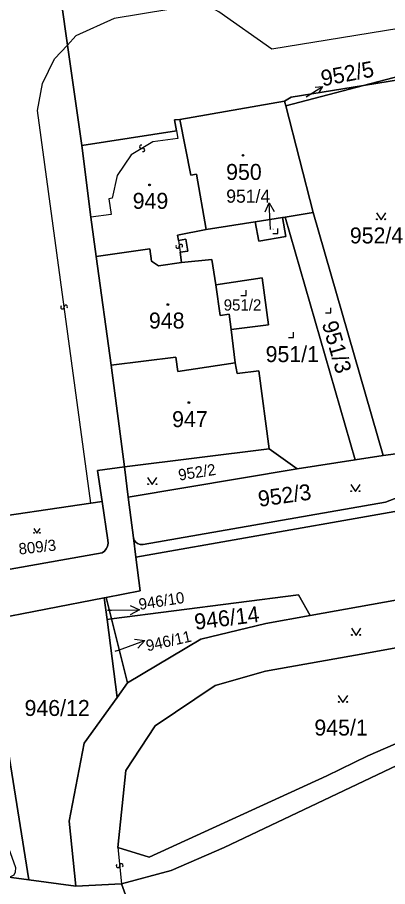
# Model space of a CAD drawing. Extents: x -600309 to -598967, y -1161267 to -1160292.
# Drawn here: x -599244.9 to -599205.5, y -1161220.2 to -1161127.6 of the extents above; entities that cross this region are included whole.
import ezdxf

# ---------------------------------------------------------------- set-up
doc = ezdxf.new("R2010")
doc.units = 0
for name, color, linetype in [('Level 1', 7, 'Continuous'), ('Level 13', 7, 'Continuous'), ('Level 3', 7, 'Continuous'), ('Level 4', 7, 'Continuous'), ('Level 5', 7, 'Continuous'), ('Level 57', 7, 'Continuous'), ('Level 60', 7, 'Continuous'), ('Vrstva 60', 7, 'Continuous')]:
    doc.layers.add(name, color=color, linetype=linetype)

msp = doc.modelspace()

# ---------------------------------------------------------------- linework, layer by layer
at = {"layer": 'Level 1'}
for points in [[(-599240.86, -1161121.69), (-599239.6, -1161130.5)], [(-599166.68, -1161128.1), (-599167.25, -1161124.11), (-599208.04, -1161134.81)], [(-599166.68, -1161128.1), (-599167.3, -1161128.2), (-599208.04, -1161134.81)], [(-599239.6, -1161130.5), (-599238.08, -1161141.2)], [(-599216.47, -1161136.47), (-599215.77, -1161136.06), (-599208.04, -1161134.81)], [(-599216.34, -1161136.99), (-599208.04, -1161134.81)], [(-599227.63, -1161138.44), (-599216.47, -1161136.47)], [(-599216.47, -1161136.47), (-599216.34, -1161136.99)], [(-599213.4, -1161148.37), (-599216.34, -1161136.99)], [(-599227.97, -1161139.66), (-599228.21, -1161138.49), (-599227.63, -1161138.44)], [(-599227.63, -1161138.44), (-599226.44, -1161144.38), (-599225.86, -1161144.27), (-599224.82, -1161150.17)], [(-599238.08, -1161141.2), (-599227.97, -1161139.66)], [(-599238.08, -1161141.2), (-599237.1, -1161148.85)], [(-599213.4, -1161148.37), (-599216.38, -1161148.84)], [(-599213.4, -1161148.37), (-599205.95, -1161174.25)], [(-599237.1, -1161148.85), (-599236.54, -1161153.03)], [(-599219.58, -1161149.34), (-599216.67, -1161148.89)], [(-599216.67, -1161148.89), (-599216.32, -1161150.91), (-599219.22, -1161151.4), (-599219.58, -1161149.34)], [(-599216.67, -1161148.89), (-599216.38, -1161148.84)], [(-599216.38, -1161148.84), (-599208.93, -1161174.71)], [(-599224.82, -1161150.17), (-599227.86, -1161150.77), (-599227.78, -1161151.33)], [(-599224.82, -1161150.17), (-599219.58, -1161149.34)], [(-599227.78, -1161151.33), (-599226.97, -1161151.2), (-599226.79, -1161152.47), (-599227.6, -1161152.59)], [(-599236.54, -1161153.03), (-599230.83, -1161152.22), (-599230.63, -1161153.54), (-599229.9, -1161154.05), (-599227.46, -1161153.69)], [(-599227.6, -1161152.59), (-599227.46, -1161153.69)], [(-599236.54, -1161153.03), (-599234.96, -1161164.64)], [(-599227.46, -1161153.69), (-599224.21, -1161153.36), (-599223.8, -1161156.07)], [(-599223.8, -1161156.07), (-599218.86, -1161155.32), (-599218.19, -1161160.32), (-599222.16, -1161160.82)], [(-599223.8, -1161156.07), (-599223.31, -1161159.32), (-599222.37, -1161159.18), (-599222.16, -1161160.82)], [(-599221.71, -1161164.39), (-599222.16, -1161160.82)], [(-599234.96, -1161164.64), (-599228.06, -1161163.79), (-599227.84, -1161165.3), (-599221.71, -1161164.39)], [(-599234.96, -1161164.64), (-599233.53, -1161175.48)], [(-599221.71, -1161164.39), (-599221.52, -1161165.53), (-599219.21, -1161165.24), (-599218.09, -1161173.54)], [(-599232.57, -1161183.04), (-599232.48, -1161183.29), (-599232.32, -1161183.5), (-599232.14, -1161183.65), (-599231.85, -1161183.75), (-599231.55, -1161183.74), (-599205.71, -1161179.24), (-599203.58, -1161178.41), (-599201.35, -1161176.43), (-599198.94, -1161173.34)], [(-599159.62, -1161172.48), (-599173.52, -1161173.95), (-599178.99, -1161175.18), (-599193.62, -1161178.28), (-599232.3, -1161185.1)], [(-599198.94, -1161173.34), (-599205.95, -1161174.25)], [(-599218.09, -1161173.54), (-599233.53, -1161175.48)], [(-599215.11, -1161175.67), (-599218.09, -1161173.54)], [(-599205.95, -1161174.25), (-599208.93, -1161174.71)], [(-599215.11, -1161175.67), (-599208.93, -1161174.71)], [(-599233.53, -1161175.48), (-599236.4, -1161175.84), (-599235.91, -1161179.17)], [(-599233.53, -1161175.48), (-599233.12, -1161178.7)], [(-599215.11, -1161175.67), (-599233.12, -1161178.7)], [(-599232.57, -1161183.04), (-599233.12, -1161178.7)], [(-599237.12, -1161179.35), (-599249.7, -1161181.2)], [(-599235.91, -1161179.17), (-599235.31, -1161183.28), (-599235.27, -1161183.61), (-599235.33, -1161183.94), (-599235.47, -1161184.22), (-599235.67, -1161184.46), (-599235.92, -1161184.63), (-599248.95, -1161186.94)], [(-599235.91, -1161179.17), (-599237.12, -1161179.35)], [(-599163.1, -1161182.7), (-599163.18, -1161182.24), (-599213.74, -1161191.32)], [(-599232.57, -1161183.04), (-599232.3, -1161185.1)], [(-599235.48, -1161189.38), (-599231.85, -1161188.68), (-599232.3, -1161185.1)], [(-599213.74, -1161191.32), (-599214.99, -1161189.11), (-599234.9, -1161191.67)], [(-599235.69, -1161189.42), (-599248.17, -1161191.83)], [(-599235.48, -1161189.38), (-599235.69, -1161189.42)], [(-599235.69, -1161189.42), (-599235.39, -1161191.73)], [(-599235.48, -1161189.38), (-599234.9, -1161191.67)], [(-599161.82, -1161189.5), (-599186.71, -1161199.25), (-599198.82, -1161204.61), (-599222.89, -1161216.04), (-599228.56, -1161218.5), (-599233.84, -1161219.9)], [(-599234.25, -1161216.06), (-599233.37, -1161207.83), (-599230.27, -1161203.06), (-599223.86, -1161198.78), (-599218.5, -1161197.24), (-599207.91, -1161195.38), (-599204.21, -1161194.67), (-599179.39, -1161190.37), (-599178.01, -1161193.44)], [(-599248.17, -1161191.83), (-599243.72, -1161219.5)], [(-599235.39, -1161191.73), (-599234.9, -1161191.67)], [(-599235.39, -1161191.73), (-599234.32, -1161200.06)], [(-599234.9, -1161191.67), (-599233.19, -1161198.49)], [(-599233.19, -1161198.49), (-599225.39, -1161193.83), (-599218.45, -1161192.16), (-599213.74, -1161191.32)], [(-599178.01, -1161193.44), (-599207.58, -1161206.28), (-599211.95, -1161208.39), (-599230.9, -1161217.06), (-599234.25, -1161216.06)], [(-599233.19, -1161198.49), (-599234.32, -1161200.06)], [(-599238.72, -1161220.17), (-599239.43, -1161213.23), (-599237.82, -1161204.91), (-599234.32, -1161200.06)], [(-599246.09, -1161219.18), (-599243.72, -1161219.5)], [(-599243.72, -1161219.5), (-599238.72, -1161220.17)], [(-599238.72, -1161220.17), (-599233.84, -1161219.9)], [(-599233.84, -1161219.9), (-599223.3, -1161248.82)]]:
    msp.add_lwpolyline(points, dxfattribs=at)
at = {"layer": 'Level 13'}
for centre, start, end in [((-599231.735, -1161141.362), 68.37668, 300.96668), ((-599231.546, -1161141.679), 248.59114, 120.68913), ((-599227.872, -1161151.985), 135.28838, 7.87838), ((-599227.507, -1161151.936), 315.50284, 187.60083), ((-599240.143, -1161158.443), 135.08477, 7.18276), ((-599239.778, -1161158.396), 314.87031, 187.46031), ((-599234.223, -1161217.999), 133.25271, 5.84271), ((-599233.856, -1161217.962), 313.46716, 185.56516)]:
    msp.add_arc(centre, 0.184, start, end, dxfattribs=at)
at = {"layer": 'Level 3'}
for points in [[(-599101.43, -1161117.43), (-599109.99, -1161109.28), (-599114.44, -1161108.57), (-599116.4, -1161108.6), (-599124.79, -1161109.79), (-599126.3, -1161110.5), (-599127.38, -1161111.59), (-599131.31, -1161116.83), (-599217.8, -1161130.93), (-599223.47, -1161126.97), (-599224.65, -1161126.32), (-599225.79, -1161126.22), (-599234.64, -1161127.69), (-599238.7, -1161129.53), (-599239.6, -1161130.5)], [(-599237.12, -1161179.35), (-599242.79, -1161137.48), (-599242.25, -1161134.62), (-599240.97, -1161131.96), (-599239.6, -1161130.5)], [(-599227.97, -1161139.66), (-599227.83, -1161140.47), (-599230.49, -1161140.82), (-599232.8, -1161142.22), (-599234.32, -1161144.41), (-599234.84, -1161146.81), (-599235.2, -1161146.88), (-599234.96, -1161148.55), (-599237.1, -1161148.85)], [(-599227.78, -1161151.33), (-599227.6, -1161152.59)], [(-599234.25, -1161216.06), (-599233.84, -1161219.9)]]:
    msp.add_lwpolyline(points, dxfattribs=at)
at = {"layer": 'Level 5'}
for points in [[(-599206.671, -1161148.38), (-599206.17, -1161149.13), (-599205.67, -1161148.38)], [(-599217.71, -1161150.6), (-599217.16, -1161150.6), (-599217.16, -1161150.05)], [(-599221.11, -1161157.2), (-599220.56, -1161157.2), (-599220.56, -1161156.65)], [(-599212.09, -1161159.05), (-599211.54, -1161159.05), (-599211.54, -1161158.5)], [(-599216.04, -1161161.67), (-599215.49, -1161161.67), (-599215.49, -1161161.12)], [(-599231.061, -1161176.61), (-599230.56, -1161177.36), (-599230.06, -1161176.61)], [(-599209.411, -1161177.36), (-599208.91, -1161178.11), (-599208.41, -1161177.36)], [(-599243.201, -1161182.03), (-599242.86, -1161182.54), (-599242.52, -1161182.03)], [(-599209.341, -1161192.68), (-599208.84, -1161193.43), (-599208.34, -1161192.68)], [(-599210.731, -1161199.83), (-599210.23, -1161200.58), (-599209.73, -1161199.83)]]:
    msp.add_lwpolyline(points, dxfattribs=at)
for centre, radius in [((-599220.89, -1161142.26), 0.09), ((-599220.89, -1161142.26), 0.0521), ((-599230.85, -1161145.41), 0.09), ((-599230.85, -1161145.41), 0.0521), ((-599206.62, -1161149.08), 0.05), ((-599205.721, -1161149.08), 0.05), ((-599228.9, -1161158.17), 0.09), ((-599228.9, -1161158.17), 0.0521), ((-599226.66, -1161168.61), 0.09), ((-599226.66, -1161168.61), 0.0521), ((-599231.01, -1161177.31), 0.05), ((-599230.111, -1161177.31), 0.05), ((-599209.36, -1161178.06), 0.05), ((-599208.461, -1161178.06), 0.05), ((-599243.166, -1161182.506), 0.034), ((-599242.555, -1161182.506), 0.034), ((-599209.29, -1161193.38), 0.05), ((-599208.391, -1161193.38), 0.05), ((-599210.68, -1161200.53), 0.05), ((-599209.781, -1161200.53), 0.05)]:
    msp.add_circle(centre, radius, dxfattribs=at)
at = {"layer": 'Level 57'}
for p, q in [((-599214.16, -1161136.03), (-599212.41, -1161134.91)), ((-599217.96, -1161150.18), (-599218.105, -1161147.31)), ((-599235.32, -1161190.75), (-599234.912, -1161190.747)), ((-599234.912, -1161190.747), (-599231.912, -1161190.725)), ((-599234.168, -1161194.998), (-599231.35, -1161193.97)), ((-599234.53, -1161195.13), (-599234.168, -1161194.998))]:
    msp.add_line(p, q, dxfattribs=at)
for points in [[(-599213.18, -1161134.992), (-599212.41, -1161134.91), (-599212.807, -1161135.575)], [(-599218.535, -1161148.291), (-599218.105, -1161147.31), (-599217.579, -1161148.242)], [(-599232.916, -1161190.232), (-599231.912, -1161190.725), (-599232.908, -1161191.232)], [(-599232.46, -1161193.843), (-599231.35, -1161193.97), (-599232.118, -1161194.782)]]:
    msp.add_lwpolyline(points, dxfattribs=at)
at = {"layer": 'Level 60'}
for points in [[(-599240.86, -1161121.69), (-599239.6, -1161130.5), (-599238.08, -1161141.2), (-599237.1, -1161148.85), (-599236.54, -1161153.03), (-599234.96, -1161164.64), (-599233.53, -1161175.48), (-599236.4, -1161175.84), (-599235.91, -1161179.17), (-599237.12, -1161179.35), (-599249.7, -1161181.2), (-599252.68, -1161158.51), (-599253.88, -1161149.28), (-599254.64, -1161143.96), (-599256.97, -1161138.54), (-599260.66, -1161135.91), (-599265.61, -1161135.24), (-599287.9, -1161138.96), (-599331.21, -1161148.11)], [(-599167.25, -1161124.11), (-599208.04, -1161134.81), (-599215.77, -1161136.06), (-599216.47, -1161136.47), (-599227.63, -1161138.44), (-599228.21, -1161138.49), (-599227.97, -1161139.66), (-599238.08, -1161141.2), (-599239.6, -1161130.5), (-599240.86, -1161121.69)], [(-599223.3, -1161248.82), (-599233.84, -1161219.9), (-599228.56, -1161218.5), (-599222.89, -1161216.04), (-599198.82, -1161204.61), (-599186.71, -1161199.25), (-599161.82, -1161189.5), (-599099.81, -1161165.17), (-599095.29, -1161162.55), (-599094.88, -1161161.32), (-599094.31, -1161159.35), (-599094.94, -1161155.86), (-599095.55, -1161152.16), (-599095.89, -1161150.08), (-599085.08, -1161148.21), (-599079.82, -1161147.3)], [(-599248.95, -1161186.94), (-599235.92, -1161184.63), (-599235.67, -1161184.46), (-599235.47, -1161184.22), (-599235.33, -1161183.94), (-599235.27, -1161183.61), (-599235.31, -1161183.28), (-599235.91, -1161179.17), (-599236.4, -1161175.84), (-599233.53, -1161175.48), (-599233.12, -1161178.7), (-599232.57, -1161183.04), (-599232.3, -1161185.1), (-599231.85, -1161188.68), (-599235.48, -1161189.38), (-599235.69, -1161189.42), (-599248.17, -1161191.83)]]:
    msp.add_lwpolyline(points, dxfattribs=at)
for points in [[(-599166.68, -1161128.1), (-599167.3, -1161128.2), (-599208.04, -1161134.81), (-599167.25, -1161124.11)], [(-599199.52, -1161166.7), (-599196.94, -1161166.87), (-599198.31, -1161172.17), (-599198.94, -1161173.34), (-599205.95, -1161174.25), (-599213.4, -1161148.37), (-599216.34, -1161136.99), (-599208.04, -1161134.81), (-599167.3, -1161128.2), (-599166.68, -1161128.1), (-599166.57, -1161128.91), (-599167.27, -1161128.99), (-599180.79, -1161131.24), (-599188.26, -1161134.19), (-599196.02, -1161141.28), (-599200.42, -1161150.04), (-599201.69, -1161156.94), (-599202.54, -1161166.5)], [(-599216.47, -1161136.47), (-599215.77, -1161136.06), (-599208.04, -1161134.81), (-599216.34, -1161136.99)], [(-599226.44, -1161144.38), (-599227.63, -1161138.44), (-599216.47, -1161136.47), (-599216.34, -1161136.99), (-599213.4, -1161148.37), (-599216.38, -1161148.84), (-599216.67, -1161148.89), (-599219.58, -1161149.34), (-599224.82, -1161150.17), (-599225.86, -1161144.27)], [(-599237.1, -1161148.85), (-599238.08, -1161141.2), (-599227.97, -1161139.66), (-599228.21, -1161138.49), (-599227.63, -1161138.44), (-599226.44, -1161144.38), (-599225.86, -1161144.27), (-599224.82, -1161150.17), (-599227.86, -1161150.77), (-599227.78, -1161151.33), (-599226.97, -1161151.2), (-599226.79, -1161152.47), (-599227.6, -1161152.59), (-599227.46, -1161153.69), (-599229.9, -1161154.05), (-599230.63, -1161153.54), (-599230.83, -1161152.22), (-599236.54, -1161153.03)], [(-599213.4, -1161148.37), (-599205.95, -1161174.25), (-599208.93, -1161174.71), (-599216.38, -1161148.84)], [(-599221.52, -1161165.53), (-599221.71, -1161164.39), (-599222.16, -1161160.82), (-599218.19, -1161160.32), (-599218.86, -1161155.32), (-599223.8, -1161156.07), (-599224.21, -1161153.36), (-599227.46, -1161153.69), (-599227.6, -1161152.59), (-599226.79, -1161152.47), (-599226.97, -1161151.2), (-599227.78, -1161151.33), (-599227.86, -1161150.77), (-599224.82, -1161150.17), (-599219.58, -1161149.34), (-599219.22, -1161151.4), (-599216.32, -1161150.91), (-599216.67, -1161148.89), (-599216.38, -1161148.84), (-599208.93, -1161174.71), (-599215.11, -1161175.67), (-599218.09, -1161173.54), (-599219.21, -1161165.24)], [(-599219.58, -1161149.34), (-599216.67, -1161148.89), (-599216.32, -1161150.91), (-599219.22, -1161151.4)], [(-599234.96, -1161164.64), (-599236.54, -1161153.03), (-599230.83, -1161152.22), (-599230.63, -1161153.54), (-599229.9, -1161154.05), (-599227.46, -1161153.69), (-599224.21, -1161153.36), (-599223.8, -1161156.07), (-599223.31, -1161159.32), (-599222.37, -1161159.18), (-599222.16, -1161160.82), (-599221.71, -1161164.39), (-599227.84, -1161165.3), (-599228.06, -1161163.79)], [(-599222.37, -1161159.18), (-599223.31, -1161159.32), (-599223.8, -1161156.07), (-599218.86, -1161155.32), (-599218.19, -1161160.32), (-599222.16, -1161160.82)], [(-599233.53, -1161175.48), (-599234.96, -1161164.64), (-599228.06, -1161163.79), (-599227.84, -1161165.3), (-599221.71, -1161164.39), (-599221.52, -1161165.53), (-599219.21, -1161165.24), (-599218.09, -1161173.54)], [(-599231.55, -1161183.74), (-599205.71, -1161179.24), (-599203.58, -1161178.41), (-599201.35, -1161176.43), (-599198.94, -1161173.34), (-599187.81, -1161170.91), (-599185.13, -1161175.67), (-599151.4, -1161169.47), (-599147.73, -1161164.98), (-599145.08, -1161164.71), (-599139.27, -1161164.03), (-599144.02, -1161170.83), (-599159.62, -1161172.48), (-599173.52, -1161173.95), (-599178.99, -1161175.18), (-599193.62, -1161178.28), (-599232.3, -1161185.1), (-599232.57, -1161183.04), (-599232.48, -1161183.29), (-599232.32, -1161183.5), (-599232.14, -1161183.65), (-599231.85, -1161183.75)], [(-599235.48, -1161189.38), (-599231.85, -1161188.68), (-599232.3, -1161185.1), (-599193.62, -1161178.28), (-599178.99, -1161175.18), (-599173.52, -1161173.95), (-599159.62, -1161172.48), (-599157.6, -1161180.94), (-599163.1, -1161182.7), (-599163.18, -1161182.24), (-599213.74, -1161191.32), (-599214.99, -1161189.11), (-599234.9, -1161191.67)], [(-599205.71, -1161179.24), (-599231.55, -1161183.74), (-599231.85, -1161183.75), (-599232.14, -1161183.65), (-599232.32, -1161183.5), (-599232.48, -1161183.29), (-599232.57, -1161183.04), (-599233.12, -1161178.7), (-599215.11, -1161175.67), (-599208.93, -1161174.71), (-599205.95, -1161174.25), (-599198.94, -1161173.34), (-599201.35, -1161176.43), (-599203.58, -1161178.41)], [(-599233.53, -1161175.48), (-599218.09, -1161173.54), (-599215.11, -1161175.67), (-599233.12, -1161178.7)], [(-599237.12, -1161179.35), (-599235.91, -1161179.17), (-599235.31, -1161183.28), (-599235.27, -1161183.61), (-599235.33, -1161183.94), (-599235.47, -1161184.22), (-599235.67, -1161184.46), (-599235.92, -1161184.63), (-599248.95, -1161186.94), (-599249.7, -1161181.2)], [(-599233.84, -1161219.9), (-599238.72, -1161220.17), (-599239.43, -1161213.23), (-599237.82, -1161204.91), (-599234.32, -1161200.06), (-599233.19, -1161198.49), (-599225.39, -1161193.83), (-599218.45, -1161192.16), (-599213.74, -1161191.32), (-599163.18, -1161182.24), (-599163.1, -1161182.7), (-599162.23, -1161187.33), (-599161.82, -1161189.5), (-599186.71, -1161199.25), (-599198.82, -1161204.61), (-599222.89, -1161216.04), (-599228.56, -1161218.5)], [(-599225.39, -1161193.83), (-599233.19, -1161198.49), (-599234.9, -1161191.67), (-599214.99, -1161189.11), (-599213.74, -1161191.32), (-599218.45, -1161192.16)], [(-599237.82, -1161204.91), (-599239.43, -1161213.23), (-599238.72, -1161220.17), (-599243.72, -1161219.5), (-599248.17, -1161191.83), (-599235.69, -1161189.42), (-599235.39, -1161191.73), (-599234.32, -1161200.06)], [(-599235.69, -1161189.42), (-599235.48, -1161189.38), (-599234.9, -1161191.67), (-599235.39, -1161191.73)], [(-599218.5, -1161197.24), (-599207.91, -1161195.38), (-599204.21, -1161194.67), (-599179.39, -1161190.37), (-599178.01, -1161193.44), (-599207.58, -1161206.28), (-599211.95, -1161208.39), (-599230.9, -1161217.06), (-599234.25, -1161216.06), (-599233.37, -1161207.83), (-599230.27, -1161203.06), (-599223.86, -1161198.78)], [(-599207.91, -1161195.38), (-599218.5, -1161197.24), (-599223.86, -1161198.78), (-599230.27, -1161203.06), (-599233.37, -1161207.83), (-599234.25, -1161216.06), (-599230.9, -1161217.06), (-599211.95, -1161208.39), (-599207.58, -1161206.28), (-599178.01, -1161193.44), (-599179.39, -1161190.37), (-599204.21, -1161194.67)], [(-599243.72, -1161219.5), (-599246.09, -1161219.18), (-599245.64, -1161219.13), (-599245.29, -1161218.95), (-599245.13, -1161218.63), (-599245.12, -1161218.2), (-599247.73, -1161210.93), (-599254.51, -1161204), (-599262.48, -1161201.42), (-599277.5, -1161204.03), (-599286.52, -1161205.07), (-599290.2, -1161206.59), (-599290.67, -1161205.81), (-599290.46, -1161205.68), (-599286.2, -1161202.26), (-599274.38, -1161196.56), (-599251.29, -1161192.43), (-599248.17, -1161191.83)], [(-599233.19, -1161198.49), (-599234.32, -1161200.06), (-599235.39, -1161191.73), (-599234.9, -1161191.67)]]:
    msp.add_lwpolyline(points, close=True, dxfattribs=at)
at = {"layer": 'Vrstva 60'}
msp.add_lwpolyline([(-599239.15, -1161267.031), (-599213.462, -1161267.031), (-599214.06, -1161265.3), (-599222.73, -1161240.63), (-599223.3, -1161248.82), (-599233.84, -1161219.9), (-599238.72, -1161220.17), (-599243.72, -1161219.5), (-599246.09, -1161219.18), (-599249.63, -1161237.16), (-599241.05, -1161260.89), (-599240.32, -1161263.6)], close=True, dxfattribs=at)

# ---------------------------------------------------------------- texts
at = {"layer": 'Level 4'}
for s, height, rotation, p in [('952/5', 0.1, 10.8, (-599214.16, -1161136.03)), ('951/3', 1.7, 286.2, (-599212.5, -1161160.19)), ('952/2', 1.2, 9, (-599227.69, -1161176.94)), ('952/3', 1.7, 8.1, (-599219.16, -1161179.74)), ('809/3', 1.2, 6.3, (-599244.75, -1161184.82)), ('946/10', 0.1, 9, (-599235.32, -1161190.75)), ('946/14', 1.7, 7.2, (-599225.97, -1161192.85)), ('946/11', 0.1, 12.6, (-599234.53, -1161195.13))]:
    msp.add_text(s, height=height, rotation=rotation, dxfattribs=at).set_placement(p)
for s, height, p in [('950', 1.7, (-599222.69, -1161144.88)), ('949', 1.7, (-599232.65, -1161147.96)), ('951/4', 0.1, (-599217.96, -1161150.18)), ('952/4', 1.7, (-599209.5, -1161151.65)), ('951/2', 1.2, (-599222.95, -1161158.81)), ('948', 1.7, (-599230.92, -1161160.72)), ('951/1', 1.7, (-599218.48, -1161164.3)), ('947', 1.7, (-599228.45, -1161171.23)), ('946/12', 1.7, (-599244.18, -1161202.02)), ('945/1', 1.7, (-599213.28, -1161204.11))]:
    msp.add_text(s, height=height, dxfattribs=at).set_placement(p)
at = {"layer": 'Level 57'}
for s, height, rotation, p in [('952/5', 1.7, 10.8, (-599212.41, -1161134.91)), ('946/10', 1.2, 9, (-599231.912, -1161190.725)), ('946/11', 1.2, 12.6, (-599231.088, -1161195.141))]:
    msp.add_text(s, height=height, rotation=rotation, dxfattribs=at).set_placement(p)
msp.add_text('951/4', height=1.4, dxfattribs=at).set_placement((-599222.675, -1161147.31))

doc.saveas('drawing.dxf')
